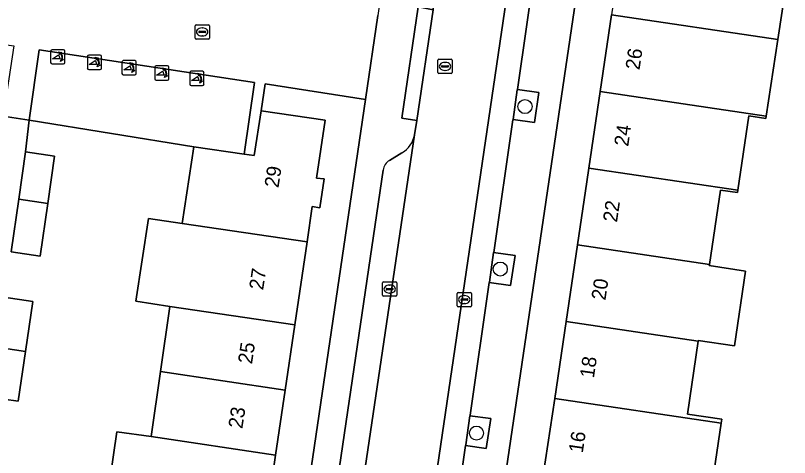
# Model space of a CAD drawing. Extents: x 164148 to 165261, y 382513 to 383432.
# Drawn here: x 164248.1 to 164302.1, y 382962.9 to 382993.7 of the extents above; entities that cross this region are included whole.
import ezdxf

# ---------------------------------------------------------------- set-up
doc = ezdxf.new("R2010")
doc.units = 0
for name, color, linetype in [('IMGEO_Boom', 7, 'Continuous'), ('IMGEO_Erf', 7, 'Continuous'), ('IMGEO_Groenvoorziening', 7, 'Continuous'), ('IMGEO_Kolk', 7, 'Continuous'), ('IMGEO_Pand', 7, 'Continuous'), ('IMGEO_Pand_nummerreeks', 7, 'Continuous'), ('IMGEO_Parkeervlak_open', 7, 'Continuous'), ('IMGEO_Poller', 7, 'Continuous'), ('IMGEO_Rijbaan_lokaal_open', 7, 'Continuous'), ('IMGEO_Rioolput', 7, 'Continuous'), ('IMGEO_Voetpad_open', 7, 'Continuous')]:
    doc.layers.add(name, color=color, linetype=linetype)

msp = doc.modelspace()

# ---------------------------------------------------------------- linework, layer by layer
at = {"layer": 'IMGEO_Boom'}
for centre in [(164283.62, 382987.338), (164281.9, 382976.026), (164280.24, 382964.602)]:
    msp.add_circle(centre, 0.489, dxfattribs=at)
at = {"layer": 'IMGEO_Erf'}
for points in [[(164291.171, 383021.984), (164278.188, 382934.213), (164285.371, 382933.164), (164285.821, 382936.306), (164285.725, 382936.32), (164281.23, 382936.985), (164281.815, 382940.929), (164281.37, 382940.995), (164281.649, 382942.874), (164282.094, 382942.808), (164282.517, 382945.656), (164283.31, 382950.998), (164284.103, 382956.338), (164284.896, 382961.68), (164285.689, 382967.022), (164286.482, 382972.362), (164287.275, 382977.705), (164287.928, 382982.106), (164288.067, 382983.046), (164288.856, 382988.388), (164289.645, 382993.73)], [(164302.056, 382997.35), (164301.247, 382992.011), (164300.437, 382986.671), (164300.413, 382986.51), (164299.219, 382986.686), (164298.455, 382981.507), (164298.432, 382981.35), (164297.238, 382981.527), (164296.473, 382976.341), (164296.461, 382976.262), (164298.991, 382975.888), (164298.223, 382970.676), (164295.693, 382971.049), (164295.685, 382970.998), (164294.938, 382965.93), (164297.337, 382965.576), (164297.296, 382965.301), (164296.508, 382959.959)], [(164260.833, 382908.792), (164272.503, 382987.831), (164265.514, 382988.929), (164265.229, 382987.03), (164269.688, 382986.378), (164269.099, 382982.348), (164269.632, 382982.3), (164269.326, 382980.293), (164268.792, 382980.375), (164268.428, 382977.911), (164267.576, 382972.135), (164266.907, 382967.603), (164266.238, 382963.071), (164265.504, 382958.099), (164264.822, 382953.482), (164264.141, 382948.866), (164263.459, 382944.249), (164262.692, 382939.056), (164262.011, 382934.439), (164261.328, 382929.813)], [(164252.7, 382931.09), (164253.372, 382935.717), (164254.043, 382940.336), (164251.678, 382940.679), (164252.432, 382945.875), (164254.797, 382945.531), (164255.468, 382950.15), (164256.139, 382954.767), (164253.792, 382955.114), (164254.463, 382959.727), (164255.186, 382964.7), (164257.561, 382964.355), (164258.219, 382968.889), (164258.877, 382973.423), (164256.504, 382973.779), (164257.371, 382979.553), (164259.733, 382979.198), (164260.536, 382984.54), (164249.057, 382986.385), (164248.815, 382984.183), (164250.832, 382983.893), (164250.355, 382980.586), (164249.829, 382976.93), (164247.812, 382977.22)], [(164247.307, 382974.069), (164249.315, 382973.774), (164248.801, 382970.283), (164248.292, 382966.82), (164246.284, 382967.115)]]:
    msp.add_lwpolyline(points, dxfattribs=at)
at = {"layer": 'IMGEO_Groenvoorziening'}
for points in [[(164283.087, 382988.517), (164283.084, 382988.494), (164282.785, 382986.445), (164284.274, 382986.225), (164284.595, 382988.316)], [(164281.435, 382977.167), (164281.137, 382975.114), (164281.134, 382975.094), (164282.609, 382974.877), (164282.93, 382976.968)], [(164279.783, 382965.814), (164279.487, 382963.781), (164279.481, 382963.741), (164280.922, 382963.529), (164281.243, 382965.62)]]:
    msp.add_lwpolyline(points, close=True, dxfattribs=at)
at = {"layer": 'IMGEO_Kolk'}
for p, q in [((164260.625, 382992.108), (164260.625, 382992.96)), ((164260.7, 382993.034), (164261.552, 382993.034)), ((164261.113, 382992.814), (164261.138, 382992.814)), ((164261.626, 382992.96), (164261.626, 382992.108)), ((164260.884, 382992.528), (164260.884, 382992.54)), ((164261.322, 382992.491), (164260.924, 382992.491)), ((164260.927, 382992.577), (164261.325, 382992.577)), ((164261.136, 382992.254), (164261.111, 382992.254)), ((164261.368, 382992.54), (164261.368, 382992.528)), ((164261.552, 382992.034), (164260.7, 382992.034)), ((164273.69, 382974.203), (164273.69, 382975.055)), ((164273.765, 382975.129), (164274.617, 382975.129)), ((164274.691, 382975.055), (164274.691, 382974.203)), ((164273.949, 382974.623), (164273.949, 382974.635)), ((164274.387, 382974.586), (164273.989, 382974.586)), ((164273.992, 382974.672), (164274.39, 382974.672)), ((164274.178, 382974.909), (164274.203, 382974.909)), ((164274.433, 382974.635), (164274.433, 382974.623)), ((164274.617, 382974.129), (164273.765, 382974.129)), ((164274.201, 382974.349), (164274.176, 382974.349)), ((164278.888, 382973.473), (164278.888, 382974.325)), ((164278.963, 382974.399), (164279.815, 382974.399)), ((164279.147, 382973.893), (164279.147, 382973.905)), ((164279.19, 382973.942), (164279.588, 382973.942)), ((164279.376, 382974.179), (164279.401, 382974.179)), ((164279.631, 382973.905), (164279.631, 382973.893)), ((164279.889, 382974.325), (164279.889, 382973.473)), ((164279.815, 382973.399), (164278.963, 382973.399)), ((164279.585, 382973.856), (164279.187, 382973.856)), ((164279.399, 382973.619), (164279.374, 382973.619))]:
    msp.add_line(p, q, dxfattribs=at)
for points in [[(164260.625, 382992.108), (164260.625, 382992.96)], [(164260.7, 382993.034), (164261.552, 382993.034)], [(164261.626, 382992.96), (164261.626, 382992.108)], [(164261.552, 382992.034), (164260.7, 382992.034)], [(164273.69, 382974.203), (164273.69, 382975.055)], [(164273.765, 382975.129), (164274.617, 382975.129)], [(164274.691, 382975.055), (164274.691, 382974.203)], [(164274.617, 382974.129), (164273.765, 382974.129)], [(164278.888, 382973.473), (164278.888, 382974.325)], [(164278.963, 382974.399), (164279.815, 382974.399)], [(164279.889, 382974.325), (164279.889, 382973.473)], [(164279.815, 382973.399), (164278.963, 382973.399)]]:
    msp.add_lwpolyline(points, dxfattribs=at)
for centre, radius, start, end in [((164260.702, 382992.958), 0.0765, 91.552, 178.448), ((164260.702, 382992.958), 0.0765, 91.552, 178.448), ((164261.55, 382992.958), 0.0765, 1.552, 88.448), ((164261.55, 382992.958), 0.0765, 1.552, 88.448), ((164260.924, 382992.537), 0.0403, 85.8775, 175.7526), ((164260.921, 382992.527), 0.0366, 178.938, 274.7102), ((164261.325, 382992.534), 0.043, 264.8664, 352.4533), ((164261.329, 382992.539), 0.0386, 1.7309, 96.639), ((164260.702, 382992.11), 0.0765, 181.552, 268.448), ((164260.702, 382992.11), 0.0765, 181.552, 268.448), ((164261.55, 382992.11), 0.0765, 271.552, 358.448), ((164261.55, 382992.11), 0.0765, 271.552, 358.448), ((164273.767, 382975.053), 0.0765, 91.552, 178.448), ((164273.767, 382975.053), 0.0765, 91.552, 178.448), ((164274.615, 382975.053), 0.0765, 1.552, 88.448), ((164274.615, 382975.053), 0.0765, 1.552, 88.448), ((164273.989, 382974.632), 0.0403, 85.8775, 175.7526), ((164273.986, 382974.622), 0.0366, 178.938, 274.7102), ((164274.39, 382974.629), 0.043, 264.8664, 352.4533), ((164274.394, 382974.634), 0.0386, 1.7309, 96.639), ((164273.767, 382974.205), 0.0765, 181.552, 268.448), ((164273.767, 382974.205), 0.0765, 181.552, 268.448), ((164274.615, 382974.205), 0.0765, 271.552, 358.448), ((164274.615, 382974.205), 0.0765, 271.552, 358.448), ((164278.965, 382974.323), 0.0765, 91.552, 178.448), ((164278.965, 382974.323), 0.0765, 91.552, 178.448), ((164279.187, 382973.902), 0.0403, 85.8775, 175.7526), ((164279.592, 382973.904), 0.0386, 1.7309, 96.639), ((164279.813, 382974.323), 0.0765, 1.552, 88.448), ((164279.813, 382974.323), 0.0765, 1.552, 88.448), ((164278.965, 382973.475), 0.0765, 181.552, 268.448), ((164278.965, 382973.475), 0.0765, 181.552, 268.448), ((164279.184, 382973.892), 0.0366, 178.938, 274.7102), ((164279.588, 382973.899), 0.043, 264.8664, 352.4533), ((164279.813, 382973.475), 0.0765, 271.552, 358.448), ((164279.813, 382973.475), 0.0765, 271.552, 358.448)]:
    msp.add_arc(centre, radius, start, end, dxfattribs=at)
for centre, major_axis, ratio, start_param, end_param in [((164261.112, 382992.534), (-0.387, 0.002), 0.722429, 4.712389, 7.853982), ((164261.137, 382992.534), (-0.39, 0.002), 0.717154, 1.570796, 4.712389), ((164274.177, 382974.629), (-0.387, 0.002), 0.722429, 4.712389, 7.853982), ((164274.202, 382974.629), (-0.39, 0.002), 0.717154, 1.570796, 4.712389), ((164279.375, 382973.899), (-0.387, 0.002), 0.722429, 4.712389, 7.853982), ((164279.4, 382973.899), (-0.39, 0.002), 0.717154, 1.570796, 4.712389)]:
    msp.add_ellipse(centre, major_axis=major_axis, ratio=ratio, start_param=start_param, end_param=end_param, dxfattribs=at)
at = {"layer": 'IMGEO_Pand'}
for points in [[(164302.056, 382997.35), (164290.434, 382999.073), (164289.645, 382993.73), (164301.247, 382992.011)], [(164301.247, 382992.011), (164289.645, 382993.73), (164288.856, 382988.388), (164300.437, 382986.671)], [(164299.219, 382986.686), (164300.413, 382986.51), (164300.437, 382986.671), (164288.856, 382988.388), (164288.067, 382983.046), (164298.455, 382981.507)], [(164259.733, 382979.198), (164268.428, 382977.911), (164268.792, 382980.375), (164269.326, 382980.293), (164269.632, 382982.3), (164269.099, 382982.348), (164269.688, 382986.378), (164265.229, 382987.03), (164264.753, 382983.919), (164264.054, 382984.022), (164260.536, 382984.54)], [(164248.34, 382980.884), (164250.355, 382980.586), (164250.832, 382983.893), (164248.815, 382984.183)], [(164297.238, 382981.527), (164298.432, 382981.35), (164298.455, 382981.507), (164288.067, 382983.046), (164287.928, 382982.106), (164287.275, 382977.705), (164296.473, 382976.341)], [(164248.34, 382980.884), (164247.812, 382977.22), (164249.829, 382976.93), (164250.355, 382980.586)], [(164259.733, 382979.198), (164257.371, 382979.553), (164256.504, 382973.779), (164258.877, 382973.423), (164267.576, 382972.135), (164268.428, 382977.911)], [(164296.461, 382976.262), (164296.473, 382976.341), (164287.275, 382977.705), (164286.482, 382972.362), (164295.685, 382970.998), (164295.693, 382971.049), (164298.223, 382970.676), (164298.991, 382975.888)], [(164246.793, 382970.58), (164248.801, 382970.283), (164249.315, 382973.774), (164247.307, 382974.069)], [(164258.219, 382968.889), (164266.907, 382967.603), (164267.576, 382972.135), (164258.877, 382973.423)], [(164295.685, 382970.998), (164286.482, 382972.362), (164285.689, 382967.022), (164297.296, 382965.301), (164297.337, 382965.576), (164294.938, 382965.93)], [(164246.793, 382970.58), (164246.284, 382967.115), (164248.292, 382966.82), (164248.801, 382970.283)], [(164258.219, 382968.889), (164257.561, 382964.355), (164266.238, 382963.071), (164266.907, 382967.603)], [(164297.296, 382965.301), (164285.689, 382967.022), (164284.896, 382961.68), (164296.508, 382959.959)], [(164265.504, 382958.099), (164266.238, 382963.071), (164257.561, 382964.355), (164255.186, 382964.7), (164254.463, 382959.727), (164256.81, 382959.386)]]:
    msp.add_lwpolyline(points, close=True, dxfattribs=at)
at = {"layer": 'IMGEO_Parkeervlak_open'}
for points in [[(164285.997, 383019.798), (164273.935, 382937.981)], [(164282.782, 382986.421), (164282.785, 382986.445), (164283.084, 382988.494), (164283.087, 382988.517), (164284.432, 382997.762), (164284.435, 382997.781), (164284.734, 382999.833), (164284.737, 382999.852), (164286.079, 383009.08), (164286.082, 383009.099), (164286.381, 383011.152), (164286.386, 383011.187), (164287.187, 383016.691)], [(164276.094, 382940.463), (164276.18, 382941.055), (164276.181, 382941.063), (164276.188, 382941.111), (164276.483, 382943.137), (164276.485, 382943.15), (164276.496, 382943.224), (164277.83, 382952.39), (164277.833, 382952.411), (164277.838, 382952.449), (164278.131, 382954.463), (164278.14, 382954.523), (164279.481, 382963.741), (164279.487, 382963.781), (164279.783, 382965.814), (164279.79, 382965.86), (164281.134, 382975.094), (164281.137, 382975.114), (164281.435, 382977.167), (164281.438, 382977.188), (164282.782, 382986.421)], [(164268.094, 382932.574), (164275.91, 382985.375)], [(164275.048, 382984.111), (164274.17, 382983.593)], [(164273.731, 382982.918), (164266.749, 382935.45)]]:
    msp.add_lwpolyline(points, dxfattribs=at)
msp.add_lwpolyline([(164260.536, 382984.54), (164264.054, 382984.022), (164264.768, 382989.02), (164249.772, 382991.276), (164249.057, 382986.385)], close=True, dxfattribs=at)
for centre, radius, start, end in [((164274.151, 382985.648), 1.78, 300.2505, 351.1645), ((164274.703, 382982.766), 0.984, 122.8104, 171.112)]:
    msp.add_arc(centre, radius, start, end, dxfattribs=at)
at = {"layer": 'IMGEO_Poller'}
for p, q in [((164250.563, 382991.202), (164250.563, 382990.395)), ((164250.563, 382991.202), (164250.563, 382990.395)), ((164251.465, 382991.297), (164250.657, 382991.297)), ((164251.465, 382991.297), (164250.657, 382991.297)), ((164251.559, 382990.395), (164251.559, 382991.202)), ((164251.559, 382990.395), (164251.559, 382991.202)), ((164253.119, 382990.823), (164253.119, 382990.016)), ((164253.119, 382990.823), (164253.119, 382990.016)), ((164254.021, 382990.918), (164253.213, 382990.918)), ((164254.021, 382990.918), (164253.213, 382990.918)), ((164254.115, 382990.016), (164254.115, 382990.823)), ((164254.115, 382990.016), (164254.115, 382990.823)), ((164250.657, 382990.3), (164251.465, 382990.3)), ((164250.657, 382990.3), (164251.465, 382990.3)), ((164255.532, 382990.439), (164255.532, 382989.632)), ((164255.532, 382990.439), (164255.532, 382989.632)), ((164256.434, 382990.534), (164255.626, 382990.534)), ((164256.434, 382990.534), (164255.626, 382990.534)), ((164256.528, 382989.632), (164256.528, 382990.439)), ((164256.528, 382989.632), (164256.528, 382990.439)), ((164257.813, 382990.081), (164257.813, 382989.274)), ((164257.813, 382990.081), (164257.813, 382989.274)), ((164258.715, 382990.176), (164257.907, 382990.176)), ((164258.715, 382990.176), (164257.907, 382990.176)), ((164258.809, 382989.274), (164258.809, 382990.081)), ((164258.809, 382989.274), (164258.809, 382990.081)), ((164253.213, 382989.921), (164254.021, 382989.921)), ((164253.213, 382989.921), (164254.021, 382989.921)), ((164260.253, 382989.695), (164260.253, 382988.888)), ((164260.253, 382989.695), (164260.253, 382988.888)), ((164261.155, 382989.79), (164260.347, 382989.79)), ((164261.155, 382989.79), (164260.347, 382989.79)), ((164261.249, 382988.888), (164261.249, 382989.695)), ((164261.249, 382988.888), (164261.249, 382989.695)), ((164255.626, 382989.537), (164256.434, 382989.537)), ((164255.626, 382989.537), (164256.434, 382989.537)), ((164257.907, 382989.179), (164258.715, 382989.179)), ((164257.907, 382989.179), (164258.715, 382989.179)), ((164260.347, 382988.793), (164261.155, 382988.793)), ((164260.347, 382988.793), (164261.155, 382988.793))]:
    msp.add_line(p, q, dxfattribs=at)
for points in [[(164251.198, 382990.653), (164250.685, 382990.653), (164251.115, 382990.928)], [(164251.242, 382991.026), (164251.23, 382990.953), (164251.105, 382991.158)], [(164251.105, 382991.158), (164251.336, 382991.092), (164251.265, 382991.06)], [(164251.258, 382990.481), (164251.324, 382990.712), (164251.354, 382990.644)], [(164253.798, 382990.647), (164253.786, 382990.574), (164253.661, 382990.779)], [(164253.661, 382990.779), (164253.892, 382990.713), (164253.821, 382990.681)], [(164251.39, 382990.617), (164251.462, 382990.606), (164251.258, 382990.481)], [(164253.754, 382990.274), (164253.241, 382990.274), (164253.671, 382990.549)], [(164253.814, 382990.102), (164253.88, 382990.333), (164253.91, 382990.265)], [(164253.946, 382990.238), (164254.018, 382990.227), (164253.814, 382990.102)], [(164256.167, 382989.89), (164255.654, 382989.89), (164256.084, 382990.165)], [(164256.211, 382990.263), (164256.199, 382990.19), (164256.074, 382990.395)], [(164256.074, 382990.395), (164256.305, 382990.329), (164256.234, 382990.297)], [(164256.227, 382989.718), (164256.293, 382989.949), (164256.323, 382989.881)], [(164256.359, 382989.854), (164256.431, 382989.843), (164256.227, 382989.718)], [(164258.448, 382989.532), (164257.935, 382989.532), (164258.365, 382989.807)], [(164258.492, 382989.905), (164258.48, 382989.832), (164258.355, 382990.037)], [(164258.355, 382990.037), (164258.586, 382989.971), (164258.515, 382989.939)], [(164258.508, 382989.36), (164258.574, 382989.591), (164258.604, 382989.523)], [(164260.932, 382989.519), (164260.92, 382989.446), (164260.795, 382989.651)], [(164260.795, 382989.651), (164261.026, 382989.585), (164260.955, 382989.553)], [(164258.64, 382989.496), (164258.712, 382989.485), (164258.508, 382989.36)], [(164260.888, 382989.146), (164260.375, 382989.146), (164260.805, 382989.421)], [(164260.948, 382988.974), (164261.014, 382989.205), (164261.044, 382989.137)], [(164261.08, 382989.11), (164261.152, 382989.099), (164260.948, 382988.974)]]:
    msp.add_lwpolyline(points, dxfattribs=at)
for centre, radius, start, end in [((164250.657, 382991.202), 0.0946, 90, 180), ((164250.657, 382991.202), 0.0946, 90, 180), ((164251.465, 382991.202), 0.0946, 0, 90), ((164251.465, 382991.202), 0.0946, 0, 90), ((164250.87, 382990.703), 0.332, 351.3247, 42.4854), ((164250.884, 382990.713), 0.476, 351.7527, 41.1691), ((164250.884, 382990.713), 0.516, 349.3569, 42.2912), ((164253.213, 382990.823), 0.0946, 90, 180), ((164253.213, 382990.823), 0.0946, 90, 180), ((164253.44, 382990.334), 0.476, 351.7527, 41.1691), ((164253.44, 382990.334), 0.516, 349.3569, 42.2912), ((164254.021, 382990.823), 0.0946, 0, 90), ((164254.021, 382990.823), 0.0946, 0, 90), ((164250.657, 382990.395), 0.0946, 180, 270), ((164250.657, 382990.395), 0.0946, 180, 270), ((164251.465, 382990.395), 0.0946, 270, 0), ((164251.465, 382990.395), 0.0946, 270, 0), ((164253.426, 382990.324), 0.332, 351.3247, 42.4854), ((164255.626, 382990.439), 0.0946, 90, 180), ((164255.626, 382990.439), 0.0946, 90, 180), ((164255.839, 382989.94), 0.332, 351.3247, 42.4854), ((164255.853, 382989.95), 0.476, 351.7527, 41.1691), ((164255.853, 382989.95), 0.516, 349.3569, 42.2912), ((164256.434, 382990.439), 0.0946, 0, 90), ((164256.434, 382990.439), 0.0946, 0, 90), ((164257.907, 382990.081), 0.0946, 90, 180), ((164257.907, 382990.081), 0.0946, 90, 180), ((164258.715, 382990.081), 0.0946, 0, 90), ((164258.715, 382990.081), 0.0946, 0, 90), ((164253.213, 382990.016), 0.0946, 180, 270), ((164253.213, 382990.016), 0.0946, 180, 270), ((164254.021, 382990.016), 0.0946, 270, 0), ((164254.021, 382990.016), 0.0946, 270, 0), ((164255.626, 382989.632), 0.0946, 180, 270), ((164255.626, 382989.632), 0.0946, 180, 270), ((164256.434, 382989.632), 0.0946, 270, 0), ((164256.434, 382989.632), 0.0946, 270, 0), ((164258.12, 382989.582), 0.332, 351.3247, 42.4854), ((164258.134, 382989.592), 0.476, 351.7527, 41.1691), ((164258.134, 382989.592), 0.516, 349.3569, 42.2912), ((164260.347, 382989.695), 0.0946, 90, 180), ((164260.347, 382989.695), 0.0946, 90, 180), ((164260.574, 382989.206), 0.516, 349.3569, 42.2912), ((164261.155, 382989.695), 0.0946, 0, 90), ((164261.155, 382989.695), 0.0946, 0, 90), ((164257.907, 382989.274), 0.0946, 180, 270), ((164257.907, 382989.274), 0.0946, 180, 270), ((164258.715, 382989.274), 0.0946, 270, 0), ((164258.715, 382989.274), 0.0946, 270, 0), ((164260.56, 382989.196), 0.332, 351.3247, 42.4854), ((164260.574, 382989.206), 0.476, 351.7527, 41.1691), ((164260.347, 382988.888), 0.0946, 180, 270), ((164260.347, 382988.888), 0.0946, 180, 270), ((164261.155, 382988.888), 0.0946, 270, 0), ((164261.155, 382988.888), 0.0946, 270, 0)]:
    msp.add_arc(centre, radius, start, end, dxfattribs=at)
at = {"layer": 'IMGEO_Rijbaan_lokaal_open'}
for points in [[(164280.514, 383016.518), (164277.25, 382994.351), (164277.211, 382994.075), (164276.079, 382986.366), (164275.91, 382985.375), (164268.094, 382932.574), (164267.789, 382930.331), (164264.507, 382908.099), (164262.402, 382894.251), (164267.326, 382893.52), (164269.536, 382908.558), (164269.642, 382909.28), (164272.102, 382925.91), (164272.225, 382926.604), (164272.552, 382928.781), (164273.761, 382936.824), (164273.935, 382937.981), (164285.997, 383019.798)], [(164232.356, 382993.76), (164232.112, 382991.925), (164231.678, 382988.803), (164232.367, 382988.7), (164233.128, 382993.672), (164248.002, 382991.565), (164247.26, 382986.674), (164249.057, 382986.385), (164249.772, 382991.276), (164264.768, 382989.02), (164264.054, 382984.022), (164264.753, 382983.919), (164265.229, 382987.03), (164265.514, 382988.929), (164272.503, 382987.831), (164273.356, 382993.681)]]:
    msp.add_lwpolyline(points, dxfattribs=at)
at = {"layer": 'IMGEO_Rioolput'}
for p, q in [((164277.625, 382990.633), (164278.477, 382990.633)), ((164277.55, 382989.707), (164277.55, 382990.559)), ((164277.809, 382990.127), (164277.809, 382990.139)), ((164278.247, 382990.09), (164277.849, 382990.09)), ((164277.852, 382990.176), (164278.25, 382990.176)), ((164278.038, 382990.413), (164278.063, 382990.413)), ((164278.293, 382990.139), (164278.293, 382990.127)), ((164278.551, 382990.559), (164278.551, 382989.707)), ((164278.477, 382989.633), (164277.625, 382989.633)), ((164278.061, 382989.853), (164278.036, 382989.853))]:
    msp.add_line(p, q, dxfattribs=at)
for points in [[(164277.625, 382990.633), (164278.477, 382990.633)], [(164277.55, 382989.707), (164277.55, 382990.559)], [(164278.551, 382990.559), (164278.551, 382989.707)], [(164278.477, 382989.633), (164277.625, 382989.633)]]:
    msp.add_lwpolyline(points, dxfattribs=at)
for centre, radius, start, end in [((164277.627, 382990.557), 0.0765, 91.552, 178.448), ((164277.627, 382990.557), 0.0765, 91.552, 178.448), ((164278.475, 382990.557), 0.0765, 1.552, 88.448), ((164278.475, 382990.557), 0.0765, 1.552, 88.448), ((164277.849, 382990.136), 0.0403, 85.8775, 175.7526), ((164277.846, 382990.126), 0.0366, 178.938, 274.7102), ((164278.25, 382990.133), 0.043, 264.8664, 352.4533), ((164278.254, 382990.138), 0.0386, 1.7309, 96.639), ((164277.627, 382989.709), 0.0765, 181.552, 268.448), ((164277.627, 382989.709), 0.0765, 181.552, 268.448), ((164278.475, 382989.709), 0.0765, 271.552, 358.448), ((164278.475, 382989.709), 0.0765, 271.552, 358.448)]:
    msp.add_arc(centre, radius, start, end, dxfattribs=at)
for centre, major_axis, ratio, start_param, end_param in [((164278.037, 382990.133), (-0.387, 0.002), 0.722429, 4.712389, 7.853982), ((164278.062, 382990.133), (-0.39, 0.002), 0.717154, 1.570796, 4.712389)]:
    msp.add_ellipse(centre, major_axis=major_axis, ratio=ratio, start_param=start_param, end_param=end_param, dxfattribs=at)
at = {"layer": 'IMGEO_Voetpad_open'}
for points in [[(164277.599, 382930.234), (164278.188, 382934.213), (164291.171, 383021.984), (164291.752, 383025.908), (164291.869, 383026.7), (164292.499, 383030.912), (164279.108, 383032.842), (164276.628, 383033.326), (164267.895, 383034.634), (164259.465, 383035.864), (164256.481, 383036.306), (164254.721, 383036.566), (164251.734, 383037.008), (164243.28, 383038.25), (164234.568, 383039.547), (164232.031, 383039.843), (164231.418, 383035.873), (164232.471, 383035.679), (164233.544, 383035.52)], [(164232.797, 383030.552), (164231.736, 383030.737), (164230.722, 383030.829), (164230.145, 383026.845), (164232.631, 383026.437), (164241.288, 383025.142), (164249.795, 383023.891), (164252.799, 383023.446), (164254.489, 383023.195), (164257.524, 383022.745), (164263.602, 383021.819), (164274.678, 383020.194), (164277.185, 383019.869), (164273.356, 382993.681), (164272.503, 382987.831), (164260.833, 382908.792), (164261.755, 382908.618), (164261.454, 382906.808), (164260.536, 382900.643), (164259.528, 382893.877)], [(164284.432, 382997.762), (164283.087, 382988.517), (164284.595, 382988.316), (164284.274, 382986.225), (164282.785, 382986.445), (164282.782, 382986.421), (164281.438, 382977.188), (164281.435, 382977.167), (164282.93, 382976.968), (164282.609, 382974.877), (164281.134, 382975.094), (164279.79, 382965.86), (164279.783, 382965.814), (164281.243, 382965.62), (164280.922, 382963.529), (164279.481, 382963.741), (164278.14, 382954.523)], [(164275.91, 382985.375), (164276.079, 382986.366), (164275.034, 382986.519), (164276.179, 382994.276), (164277.211, 382994.075), (164277.25, 382994.351)], [(164247.812, 382977.22), (164248.34, 382980.884), (164248.815, 382984.183), (164249.057, 382986.385), (164247.26, 382986.674)], [(164274.17, 382983.593), (164275.048, 382984.111)], [(164266.749, 382935.45), (164273.731, 382982.918)]]:
    msp.add_lwpolyline(points, dxfattribs=at)
msp.add_lwpolyline([(164277.211, 382994.075), (164276.179, 382994.276), (164275.034, 382986.519), (164276.079, 382986.366)], close=True, dxfattribs=at)
for centre, radius, start, end in [((164274.151, 382985.648), 1.78, 300.2505, 351.1645), ((164274.703, 382982.766), 0.984, 122.8104, 171.112)]:
    msp.add_arc(centre, radius, start, end, dxfattribs=at)

# ---------------------------------------------------------------- texts
at = {"layer": 'IMGEO_Pand_nummerreeks'}
for s, rotation, p in [('26', 81.5949, (164291.599, 382989.846)), ('24', 81.5949, (164290.812, 382984.521)), ('29', 81.2745, (164266.439, 382981.642)), ('22', 81.5548, (164290.03, 382979.242)), ('27', 81.4111, (164265.37, 382974.522)), ('20', 81.5548, (164289.224, 382973.811)), ('25', 81.4652, (164264.593, 382969.375)), ('18', 81.5548, (164288.419, 382968.392)), ('23', 81.0827, (164263.918, 382964.873)), ('16', 81.5548, (164287.645, 382963.178))]:
    msp.add_text(s, height=1, rotation=rotation, dxfattribs=at).set_placement(p)

doc.saveas('drawing.dxf')
